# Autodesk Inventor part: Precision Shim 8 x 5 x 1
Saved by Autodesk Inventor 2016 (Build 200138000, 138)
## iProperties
Created: 2015-11
Part Number: Precision Shim 8 x 5 x 1
Material: Generic
Document SubType Name: Modeling
Designer: John
Density: 1 g/cm^3
Appearance: Default
Author: John
Revision Number: ANY
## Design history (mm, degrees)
feature "Boss-Extrude1"
body "Solid1"
